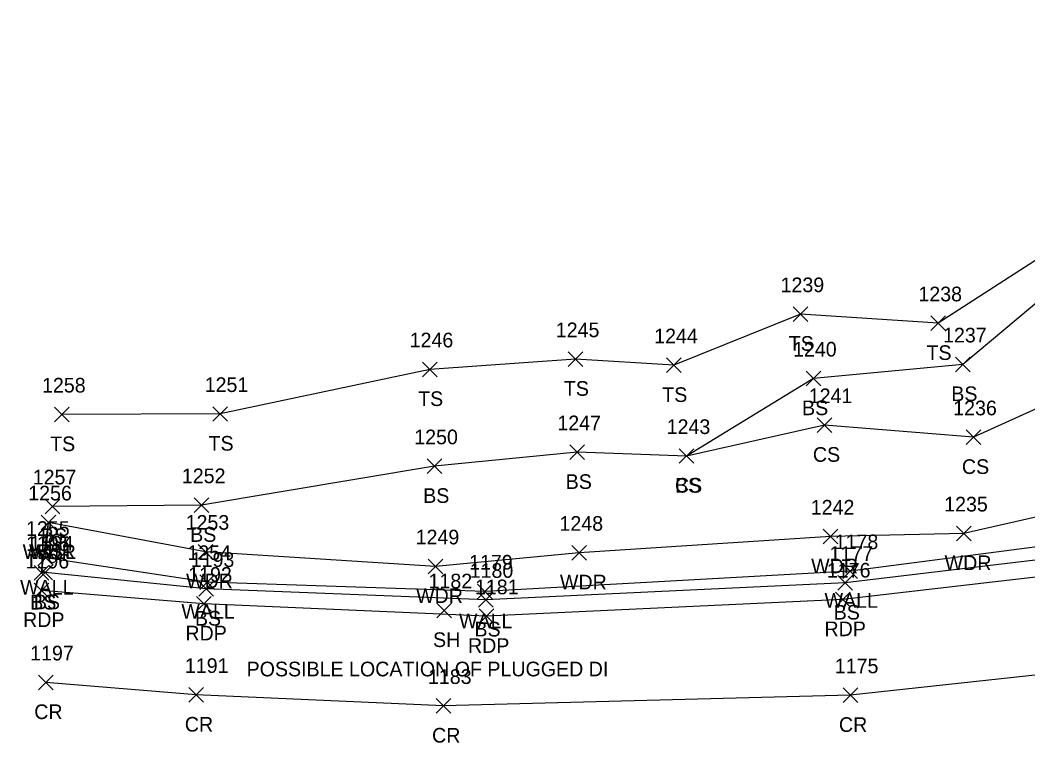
# Model space of a CAD drawing. Extents: x 1502119 to 1504100, y 606168 to 606406.
# Drawn here: x 1503598.6 to 1503736.1, y 606284.4 to 606383 of the extents above; entities that cross this region are included whole.
import ezdxf

# ---------------------------------------------------------------- set-up
doc = ezdxf.new("R2010")
doc.units = 0
for name, color, linetype in [('L_A', 7, 'Continuous'), ('L_C', 7, 'Continuous'), ('L_I', 7, 'Continuous'), ('L_TIC', 7, 'Continuous'), ('LAWA', 7, 'Continuous'), ('LELB', 7, 'Continuous'), ('LW', 7, 'Continuous'), ('P_A', 7, 'Continuous'), ('P_I', 7, 'Continuous'), ('P_TIC', 7, 'Continuous'), ('PET', 7, 'Continuous'), ('PRC', 7, 'Continuous')]:
    doc.layers.add(name, color=color, linetype=linetype)

msp = doc.modelspace()

# ---------------------------------------------------------------- linework, layer by layer
at = {"layer": 'L_TIC'}
for points in [[(1503704.03, 606341.87), (1503706.03, 606343.87)], [(1503706.03, 606341.87), (1503704.03, 606343.87)], [(1503722.82, 606340.62), (1503724.82, 606342.62)], [(1503724.82, 606340.62), (1503722.82, 606342.62)], [(1503673.36, 606335.73), (1503675.36, 606337.73)], [(1503675.36, 606335.73), (1503673.36, 606337.73)], [(1503653.48, 606334.34), (1503655.48, 606336.34)], [(1503655.48, 606334.34), (1503653.48, 606336.34)], [(1503686.78, 606334.89), (1503688.78, 606336.89)], [(1503688.78, 606334.89), (1503686.78, 606336.89)], [(1503726.18, 606335.01), (1503728.18, 606337.01)], [(1503728.18, 606335.01), (1503726.18, 606337.01)], [(1503705.81, 606333.09), (1503707.81, 606335.09)], [(1503707.81, 606333.09), (1503705.81, 606335.09)], [(1503603.28, 606328.18), (1503605.28, 606330.18)], [(1503605.28, 606328.18), (1503603.28, 606330.18)], [(1503624.89, 606328.25), (1503626.89, 606330.25)], [(1503626.89, 606328.25), (1503624.89, 606330.25)], [(1503707.3, 606326.73), (1503709.3, 606328.73)], [(1503709.3, 606326.73), (1503707.3, 606328.73)], [(1503727.63, 606325.07), (1503729.63, 606327.07)], [(1503729.63, 606325.07), (1503727.63, 606327.07)], [(1503673.57, 606323.03), (1503675.57, 606325.03)], [(1503675.57, 606323.03), (1503673.57, 606325.03)], [(1503688.48, 606322.52), (1503690.48, 606324.52)], [(1503690.48, 606322.52), (1503688.48, 606324.52)], [(1503688.48, 606322.52), (1503690.48, 606324.52)], [(1503690.48, 606322.52), (1503688.48, 606324.52)], [(1503654.14, 606321.12), (1503656.14, 606323.12)], [(1503656.14, 606321.12), (1503654.14, 606323.12)], [(1503602, 606315.64), (1503604, 606317.64)], [(1503604, 606315.64), (1503602, 606317.64)], [(1503622.35, 606315.81), (1503624.35, 606317.81)], [(1503624.35, 606315.81), (1503622.35, 606317.81)], [(1503601.45, 606313.46), (1503603.45, 606315.46)], [(1503603.45, 606313.46), (1503601.45, 606315.46)], [(1503601.45, 606313.46), (1503603.45, 606315.46)], [(1503603.45, 606313.46), (1503601.45, 606315.46)], [(1503601.45, 606313.46), (1503603.45, 606315.46)], [(1503603.45, 606313.46), (1503601.45, 606315.46)], [(1503726.35, 606311.95), (1503728.35, 606313.95)], [(1503728.35, 606311.95), (1503726.35, 606313.95)], [(1503708.14, 606311.53), (1503710.14, 606313.53)], [(1503710.14, 606311.53), (1503708.14, 606313.53)], [(1503622.87, 606309.46), (1503624.87, 606311.46)], [(1503624.87, 606309.46), (1503622.87, 606311.46)], [(1503673.87, 606309.32), (1503675.87, 606311.32)], [(1503675.87, 606309.32), (1503673.87, 606311.32)], [(1503601.1, 606308.62), (1503603.1, 606310.62)], [(1503603.1, 606308.62), (1503601.1, 606310.62)], [(1503600.52, 606306.57), (1503602.52, 606308.57)], [(1503602.52, 606306.57), (1503600.52, 606308.57)], [(1503601.03, 606306.61), (1503603.03, 606308.61)], [(1503603.03, 606306.61), (1503601.03, 606308.61)], [(1503654.25, 606307.46), (1503656.25, 606309.46)], [(1503656.25, 606307.46), (1503654.25, 606309.46)], [(1503710.84, 606306.81), (1503712.84, 606308.81)], [(1503712.84, 606306.81), (1503710.84, 606308.81)], [(1503623.1, 606305.33), (1503625.1, 606307.33)], [(1503625.1, 606305.33), (1503623.1, 606307.33)], [(1503710.14, 606305.21), (1503712.14, 606307.21)], [(1503712.14, 606305.21), (1503710.14, 606307.21)], [(1503622.99, 606304.38), (1503624.99, 606306.38)], [(1503624.99, 606304.38), (1503622.99, 606306.38)], [(1503660.97, 606304.03), (1503662.97, 606306.03)], [(1503662.97, 606304.03), (1503660.97, 606306.03)], [(1503661.13, 606302.9), (1503663.13, 606304.9)], [(1503663.13, 606302.9), (1503661.13, 606304.9)], [(1503655.43, 606301.46), (1503657.43, 606303.46)], [(1503657.43, 606301.46), (1503655.43, 606303.46)]]:
    msp.add_lwpolyline(points, dxfattribs=at)
at = {"layer": 'LAWA'}
msp.add_lwpolyline([(1503990.71, 606382.98), (1503966.9, 606374.16), (1503949.79, 606353.75), (1503942.92, 606352.55), (1503916.64, 606344.82), (1503911.63, 606340.49), (1503904.12, 606338.88), (1503887.71, 606335.33), (1503868.8, 606333.95), (1503861.91, 606334.62), (1503846, 606330.34), (1503828.45, 606328.53), (1503809.6, 606325.61), (1503789.35, 606322.82), (1503764.11, 606318.67), (1503746.35, 606317.25), (1503727.35, 606312.95), (1503709.14, 606312.53), (1503674.87, 606310.32), (1503655.25, 606308.46), (1503623.87, 606310.46), (1503602.45, 606314.46)], dxfattribs=at)
at = {"layer": 'LELB'}
for points in [[(1503923.46, 606369.4), (1503921.54, 606359.43), (1503912.25, 606356.2), (1503893.52, 606356.21), (1503867.3, 606351.42), (1503862.16, 606346.63), (1503844.87, 606345.92), (1503823.53, 606352.97), (1503809.18, 606352.42), (1503787.72, 606358.18), (1503768.27, 606361.44), (1503750.54, 606364.68), (1503739.07, 606351.46), (1503723.82, 606341.62), (1503705.03, 606342.87), (1503687.78, 606335.89), (1503674.36, 606336.73), (1503654.48, 606335.34), (1503625.89, 606329.25), (1503604.28, 606329.18)], [(1503942.92, 606352.55), (1503928.1, 606340.43), (1503910.71, 606333.69), (1503861.57, 606326.92), (1503811.33, 606319.63), (1503759.93, 606312.02), (1503711.14, 606306.21), (1503662.13, 606303.9), (1503623.99, 606305.38), (1503602.03, 606307.61), (1503601.52, 606307.57), (1503602.45, 606314.46)], [(1503846, 606330.34), (1503828.6, 606331.77), (1503810.23, 606330.74), (1503786.83, 606329.41), (1503771.08, 606342.3), (1503750.81, 606351.74), (1503742.02, 606348.43), (1503727.18, 606336.01), (1503706.81, 606334.09), (1503689.48, 606323.52), (1503674.57, 606324.03), (1503655.14, 606322.12), (1503623.35, 606316.81), (1503603, 606316.64)], [(1503786.83, 606329.41), (1503765.37, 606329.42), (1503748.33, 606335.02), (1503728.63, 606326.07), (1503708.3, 606327.73), (1503689.48, 606323.52)]]:
    msp.add_lwpolyline(points, dxfattribs=at)
at = {"layer": 'LW'}
msp.add_lwpolyline([(1503910.46, 606334.58), (1503860.8, 606328.79), (1503810.94, 606322.05), (1503761.44, 606314.27), (1503711.84, 606307.81), (1503661.97, 606305.03), (1503624.1, 606306.33), (1503602.1, 606309.62), (1503602.45, 606314.46)], dxfattribs=at)
at = {"layer": 'P_TIC'}
for points in [[(1503600.52, 606304.18), (1503602.52, 606306.18)], [(1503602.52, 606304.18), (1503600.52, 606306.18)], [(1503622.65, 606302.36), (1503624.65, 606304.36)], [(1503624.65, 606302.36), (1503622.65, 606304.36)], [(1503709.83, 606302.94), (1503711.83, 606304.94)], [(1503711.83, 606302.94), (1503709.83, 606304.94)], [(1503661.2, 606300.66), (1503663.2, 606302.66)], [(1503663.2, 606300.66), (1503661.2, 606302.66)], [(1503601.08, 606291.63), (1503603.08, 606293.63)], [(1503603.08, 606291.63), (1503601.08, 606293.63)], [(1503621.63, 606289.92), (1503623.63, 606291.92)], [(1503623.63, 606289.92), (1503621.63, 606291.92)], [(1503710.85, 606289.88), (1503712.85, 606291.88)], [(1503712.85, 606289.88), (1503710.85, 606291.88)], [(1503655.36, 606288.42), (1503657.36, 606290.42)], [(1503657.36, 606288.42), (1503655.36, 606290.42)]]:
    msp.add_lwpolyline(points, dxfattribs=at)
at = {"layer": 'PET'}
msp.add_lwpolyline([(1504085.41, 606349.16), (1504052.4, 606348.69), (1503999.05, 606344.18), (1503952.76, 606337.92), (1503910.76, 606332.19), (1503862.06, 606324.66), (1503811.74, 606316.76), (1503760.3, 606309.68), (1503710.83, 606303.94), (1503662.2, 606301.66), (1503623.65, 606303.36), (1503601.52, 606305.18)], dxfattribs=at)
at = {"layer": 'PRC'}
msp.add_lwpolyline([(1504085.68, 606335.47), (1504051.53, 606335.36), (1503999.5, 606331.04), (1503953.49, 606324.86), (1503912.24, 606318.81), (1503865.3, 606311.74), (1503812.8, 606303.34), (1503763.88, 606296.53), (1503711.85, 606290.88), (1503656.36, 606289.42), (1503622.63, 606290.92), (1503602.08, 606292.63)], dxfattribs=at)

# ---------------------------------------------------------------- texts
at = {"layer": 'L_A'}
for s, p in [('TS', (1503703.44, 606337.87)), ('TS', (1503722.23, 606336.62)), ('TS', (1503672.77, 606331.73)), ('TS', (1503652.89, 606330.34)), ('TS', (1503686.19, 606330.89)), ('BS', (1503725.62, 606331.01)), ('BS', (1503705.26, 606329.09)), ('TS', (1503624.3, 606324.25)), ('TS', (1503602.69, 606324.18)), ('CS', (1503706.74, 606322.73)), ('CS', (1503727.07, 606321.07)), ('BS', (1503673.02, 606319.03)), ('CS', (1503687.92, 606318.52)), ('BS', (1503687.92, 606318.52)), ('BS', (1503653.58, 606317.12)), ('BS', (1503601.44, 606311.64)), ('BS', (1503621.79, 606311.81)), ('WALL', (1503598.94, 606309.46)), ('WDR', (1503599.81, 606309.46)), ('BS', (1503600.89, 606309.46)), ('WDR', (1503724.71, 606307.95)), ('WDR', (1503706.5, 606307.53)), ('WDR', (1503621.23, 606305.46)), ('WDR', (1503672.23, 606305.32)), ('WALL', (1503598.59, 606304.62)), ('BS', (1503599.97, 606302.57)), ('BS', (1503600.47, 606302.61)), ('WDR', (1503652.61, 606303.46)), ('WALL', (1503708.33, 606302.81)), ('WALL', (1503620.59, 606301.33)), ('BS', (1503709.58, 606301.21)), ('BS', (1503622.44, 606300.38)), ('WALL', (1503658.46, 606300.03)), ('BS', (1503660.57, 606298.9)), ('SH', (1503654.92, 606297.46))]:
    msp.add_text(s, height=2, dxfattribs=at).set_placement(p)
at = {"layer": 'L_C'}
msp.add_text('POSSIBLE LOCATION OF PLUGGED DI', height=2, dxfattribs=at).set_placement((1503629.49, 606293.46))
at = {"layer": 'L_I'}
for s, p in [('1239', (1503702.33, 606345.87)), ('1238', (1503721.13, 606344.62)), ('1245', (1503671.67, 606339.73)), ('1246', (1503651.73, 606338.34)), ('1244', (1503685.09, 606338.89)), ('1237', (1503724.49, 606339.01)), ('1240', (1503704.03, 606337.09)), ('1258', (1503601.58, 606332.18)), ('1251', (1503623.77, 606332.25)), ('1241', (1503706.17, 606330.73)), ('1236', (1503725.88, 606329.07)), ('1247', (1503671.88, 606327.03)), ('1243', (1503686.79, 606326.52)), ('1243', (1503686.79, 606326.52)), ('1250', (1503652.36, 606325.12)), ('1257', (1503600.31, 606319.64)), ('1252', (1503620.66, 606319.81)), ('1256', (1503599.7, 606317.46)), ('1256', (1503599.7, 606317.46)), ('1256', (1503599.7, 606317.46)), ('1242', (1503706.45, 606315.53)), ('1235', (1503724.65, 606315.95)), ('1253', (1503621.17, 606313.46)), ('1248', (1503672.17, 606313.32)), ('1255', (1503599.4, 606312.62)), ('1195', (1503599.4, 606310.57)), ('1194', (1503599.91, 606310.61)), ('1249', (1503652.55, 606311.46)), ('1178', (1503709.71, 606310.81)), ('1254', (1503621.41, 606309.33)), ('1177', (1503709.01, 606309.21)), ('1193', (1503621.87, 606308.38)), ('1179', (1503659.84, 606308.03)), ('1180', (1503659.92, 606306.9)), ('1182', (1503654.31, 606305.46))]:
    msp.add_text(s, height=2, dxfattribs=at).set_placement(p)
at = {"layer": 'P_A'}
for s, p in [('RDP', (1503599, 606300.18)), ('RDP', (1503621.14, 606298.36)), ('RDP', (1503708.32, 606298.94)), ('RDP', (1503659.69, 606296.66)), ('CR', (1503600.52, 606287.63)), ('CR', (1503621.06, 606285.92)), ('CR', (1503710.29, 606285.88)), ('CR', (1503654.79, 606284.42))]:
    msp.add_text(s, height=2, dxfattribs=at).set_placement(p)
at = {"layer": 'P_I'}
for s, p in [('1196', (1503599.33, 606308.18)), ('1192', (1503621.52, 606306.36)), ('1176', (1503708.65, 606306.94)), ('1181', (1503660.64, 606304.66)), ('1197', (1503599.96, 606295.63)), ('1191', (1503621.07, 606293.92)), ('1175', (1503709.73, 606293.88)), ('1183', (1503654.23, 606292.42))]:
    msp.add_text(s, height=2, dxfattribs=at).set_placement(p)

doc.saveas('drawing.dxf')
